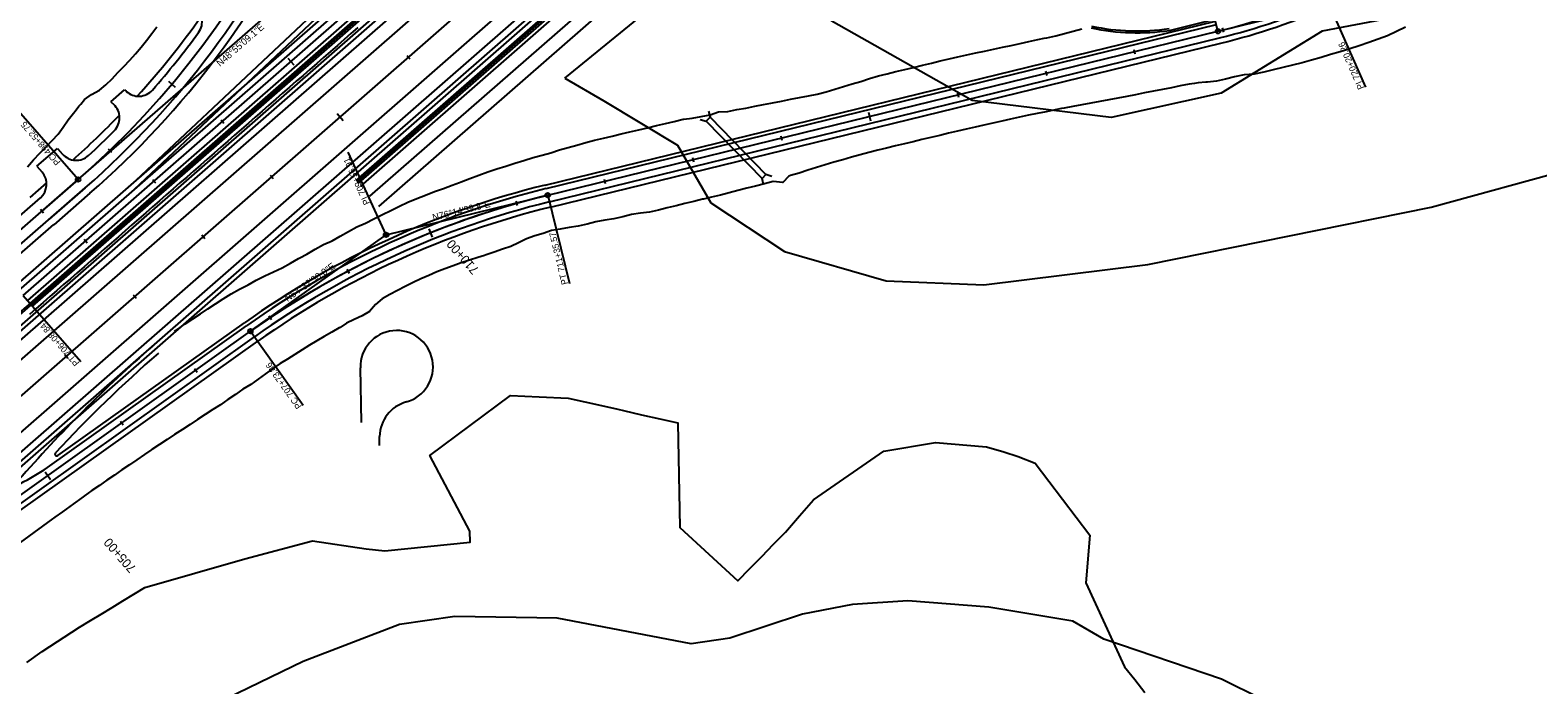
# Model space of a CAD drawing. Extents: x 1300404 to 1323571, y 234004 to 252077.
# Drawn here: x 1309592 to 1311251, y 239629 to 240349 of the extents above; entities that cross this region are included whole.
import ezdxf

# ---------------------------------------------------------------- set-up
doc = ezdxf.new("R2010")
doc.units = 0
for name, color, linetype in [('R_Barrier Wall', 7, 'Continuous'), ('R_Box Culvert', 7, 'Continuous'), ('R_Const Limits', 7, 'Continuous'), ('R_Draft', 7, 'Continuous'), ('R_Flooplain', 7, 'Continuous'), ('R_Future', 7, 'Continuous'), ('R_Horz Alg Annot', 7, 'Continuous'), ('R_Horz Alg Annot Leader', 7, 'Continuous'), ('R_Horz Alg Major Ticks', 7, 'Continuous'), ('R_Horz Alg Minor Ticks', 7, 'Continuous'), ('R_Horz Alg Station Annot', 7, 'Continuous'), ('R_Horz Alg Tangents', 7, 'Continuous'), ('R_Horz Alg Tangents Text', 7, 'Continuous'), ('R_Lane Edge', 7, 'Continuous'), ('R_Proposed', 7, 'Continuous'), ('R_Shoulder', 7, 'Continuous')]:
    doc.layers.add(name, color=color, linetype=linetype)

msp = doc.modelspace()

# ---------------------------------------------------------------- linework, layer by layer
at = {"layer": 'R_Barrier Wall'}
for p, q in [((1309593.6, 240046.8), (1310899.2, 241188.4)), ((1309594.9, 240045.3), (1310900.5, 241186.9)), ((1309593.6, 240046.8), (1309594.9, 240045.3))]:
    msp.add_line(p, q, dxfattribs=at)
at = {"layer": 'R_Box Culvert'}
for p, q in [((1310338.6, 240259.8), (1310340.3, 240253.1)), ((1310329.3, 240250.8), (1310336, 240248.9)), ((1310340.3, 240253.1), (1310336, 240248.9)), ((1310336, 240248.9), (1310397.4, 240185.8)), ((1310340.3, 240253.1), (1310401.7, 240190)), ((1310401.7, 240190), (1310397.4, 240185.8)), ((1310399.1, 240179.1), (1310397.4, 240185.8)), ((1310408.3, 240188.1), (1310401.7, 240190))]:
    msp.add_line(p, q, dxfattribs=at)
at = {"layer": 'R_Const Limits'}
for points in [[(1311105.3, 240352.3), (1311095.4, 240347.4), (1311085.4, 240342.8), (1311075.1, 240339), (1311064.7, 240335.3), (1311054.3, 240331.7), (1311043.9, 240328.3), (1311042.8, 240328), (1311033.3, 240325.3), (1311022.7, 240322.4), (1311012.4, 240318.9), (1311001.9, 240315.9), (1310991.4, 240313.2), (1310980.8, 240310.6), (1310970.2, 240308.1), (1310959.7, 240305.5), (1310949.2, 240302.9), (1310938.6, 240300.6), (1310927.6, 240300), (1310917.2, 240297.5), (1310907.1, 240294.9), (1310897.3, 240293), (1310887.3, 240291.9), (1310885.6, 240291.7), (1310877.2, 240290.9), (1310872.9, 240290.3), (1310867.3, 240289.5), (1310857.4, 240287.6), (1310847.7, 240285.5), (1310837.8, 240283.6), (1310827.9, 240281.9), (1310818.1, 240280), (1310808.3, 240278), (1310798.5, 240276.1), (1310788.7, 240274.1), (1310778.8, 240272.2), (1310768.9, 240270.6), (1310759.1, 240268.7), (1310749.2, 240267), (1310739.4, 240265), (1310729.6, 240263.2), (1310726.7, 240262.7), (1310719.7, 240261.3), (1310709.9, 240259.3), (1310700.1, 240257.4), (1310690.3, 240255.3), (1310680.6, 240253.1), (1310670.8, 240251), (1310661, 240248.8), (1310651.3, 240246.6), (1310641.5, 240244.4), (1310631.8, 240242.2), (1310622, 240240), (1310612.3, 240237.7), (1310602.5, 240235.5), (1310592.8, 240233.2), (1310583, 240230.9), (1310573.3, 240228.6), (1310563.6, 240226.3), (1310553.9, 240223.9), (1310544.2, 240221.6), (1310534.4, 240219.2), (1310524.7, 240216.8), (1310515, 240214.3), (1310505.4, 240211.7), (1310495.7, 240209.1), (1310486.1, 240206.4), (1310476.4, 240203.7), (1310466.9, 240200.8), (1310457.3, 240197.8), (1310447.7, 240194.8), (1310438.2, 240191.8), (1310428.6, 240188.9), (1310426.8, 240188.3), (1310420.2, 240181.2), (1310409.6, 240182.6), (1310399.9, 240180), (1310390.2, 240177.5), (1310380.5, 240175.1), (1310370.8, 240172.7), (1310361.1, 240170.1), (1310351.5, 240167.6), (1310341.7, 240165.2), (1310332.8, 240163.1), (1310332, 240162.9), (1310322.3, 240160.5), (1310312.6, 240158.2), (1310302.9, 240155.8), (1310293.1, 240153.5), (1310283.4, 240151.1), (1310273.7, 240148.8), (1310263.7, 240147.7), (1310253.8, 240146), (1310244.1, 240143.7), (1310234.3, 240141.4), (1310224.4, 240139.9), (1310214.6, 240138), (1310204.9, 240135.6), (1310195.1, 240133.3), (1310185.2, 240131.7), (1310175.3, 240130.1), (1310165.6, 240128.5), (1310156.6, 240125.3), (1310147.4, 240122.5), (1310138.3, 240119.4), (1310129.6, 240115), (1310120.9, 240111), (1310111.8, 240107.9), (1310102.8, 240104.8), (1310093.8, 240101.6), (1310092.1, 240101), (1310084.7, 240098.8), (1310075.5, 240096), (1310066.5, 240093), (1310057.5, 240089.7), (1310048.6, 240086.3), (1310039.7, 240082.9), (1310030.8, 240079.2), (1310022.1, 240075.4), (1310013.5, 240071.2), (1310004.9, 240066.9), (1309996.4, 240062.6), (1309988, 240058.1), (1309979.6, 240053.5), (1309972.1, 240047.3), (1309965.5, 240039.4), (1309957.4, 240034.5), (1309948.8, 240030.5), (1309940.1, 240026.5), (1309933.4, 240021.9), (1309932.2, 240021.3), (1309924, 240016.6), (1309915.8, 240011.9), (1309907.7, 240007), (1309899.4, 240002.3), (1309891.4, 239997.1), (1309883.4, 239992.1), (1309875.3, 239987.1), (1309867.3, 239982.1), (1309859.2, 239976.6), (1309851, 239970.9), (1309843, 239964.9), (1309834.9, 239959.1), (1309826.3, 239953.8), (1309818.1, 239948.1), (1309809.8, 239942.6), (1309801.8, 239936.6), (1309793.1, 239931.6), (1309784.7, 239926.1), (1309776.5, 239920.4), (1309768.2, 239914.9), (1309759.8, 239909.4), (1309751.2, 239904.2), (1309742.9, 239898.6), (1309734.6, 239893.1), (1309726.2, 239887.5), (1309725.1, 239886.7), (1309718, 239881.9), (1309709.7, 239876.3), (1309701.5, 239870.6), (1309693.2, 239865), (1309685, 239859.3), (1309676.7, 239853.7), (1309668.4, 239848), (1309660.2, 239842.3), (1309652.1, 239836.5), (1309645, 239831.5), (1309643.9, 239830.7), (1309635.8, 239824.9), (1309627.7, 239819), (1309619.6, 239813.1), (1309611.5, 239807.3), (1309284.5, 239568.2)], [(1309589.2, 240198.7), (1309596, 240206.3), (1309602.8, 240213.6), (1309606.8, 240217.7), (1309609.8, 240220.8), (1309616.6, 240227.7), (1309623.1, 240234.6), (1309628.7, 240242.4), (1309634.1, 240250.5), (1309640.1, 240257.8), (1309641.8, 240259.8), (1309646, 240265.2), (1309647.9, 240267.6), (1309651.9, 240272.6), (1309659.7, 240278.1), (1309668.4, 240282.8), (1309675.7, 240288.8), (1309682.4, 240295.5), (1309688.9, 240302.4), (1309695.4, 240309.2), (1309701.9, 240316.1), (1309708.3, 240323.1), (1309714.5, 240330.2), (1309720.3, 240337.6), (1309726, 240345.2), (1309731.7, 240352.8)], [(1309952.8, 240352), (1309945.2, 240345.4), (1309937.7, 240338.8), (1309930.2, 240332.3), (1309922.6, 240325.7), (1309915.1, 240319.1), (1309907.6, 240312.5), (1309900.1, 240305.9), (1309892.5, 240299.3), (1309885, 240292.8), (1309877.5, 240286.2), (1309869.9, 240279.6), (1309862.4, 240273), (1309854.9, 240266.4), (1309847.4, 240259.9), (1309839.8, 240253.3), (1309832.3, 240246.7), (1309824.8, 240240.1), (1309817.2, 240233.5), (1309809.7, 240226.9), (1309802.2, 240220.4), (1309794.7, 240213.8), (1309787.1, 240207.2), (1309779.6, 240200.6), (1309772.1, 240194), (1309764.6, 240187.4), (1309757, 240180.9), (1309749.5, 240174.3), (1309742, 240167.7), (1309734.4, 240161.1), (1309726.9, 240154.5), (1309719.4, 240147.9), (1309711.9, 240141.4), (1309704.3, 240134.8), (1309696.8, 240128.2), (1309689.3, 240121.6), (1309681.7, 240115), (1309674.2, 240108.5), (1309666.7, 240101.9), (1309659.2, 240095.3), (1309651.6, 240088.7), (1309644.1, 240082.1), (1309636.6, 240075.5), (1309629.1, 240069), (1309621.5, 240062.4), (1309614, 240055.8), (1309606.5, 240049.2), (1309598.9, 240042.6), (1309591.4, 240036)], [(1309751.2, 240017.8), (1309754.6, 240020.1), (1309762.9, 240025.7), (1309771.2, 240031.2), (1309779.6, 240036.7), (1309787.9, 240042.3), (1309796.2, 240047.8), (1309804.7, 240053.2), (1309813.3, 240058.8), (1309822.6, 240063.9), (1309832, 240068.7), (1309841, 240073.9), (1309850.5, 240078.5), (1309860, 240083.1), (1309869.6, 240087.3), (1309878.6, 240092.5), (1309887.6, 240097.6), (1309888.9, 240098.3), (1309896.8, 240102.6), (1309905.7, 240107.9), (1309914.8, 240113), (1309924.4, 240117.1), (1309933.4, 240122.4), (1309942.4, 240127.6), (1309951.6, 240132.6), (1309961.2, 240136.5), (1309970.5, 240141.3), (1309979.7, 240146.1), (1309989.1, 240150.6), (1309998.4, 240155.3), (1310007.9, 240159.6), (1310017.5, 240163.6), (1310027.2, 240167.6), (1310036.9, 240171.3), (1310046.8, 240174.7), (1310056.5, 240178.4), (1310064.4, 240181.4), (1310066.3, 240182), (1310076, 240185.8), (1310085.8, 240189.4), (1310095.6, 240193.2), (1310105.5, 240196.4), (1310115.5, 240199.5), (1310125.5, 240202.5), (1310135.5, 240205.6), (1310145.5, 240208.7), (1310155.4, 240211.5), (1310165, 240214.2), (1310174.6, 240217.2), (1310184.2, 240220), (1310193.8, 240222.6), (1310203.5, 240225.4), (1310213.1, 240228), (1310222.9, 240230.2), (1310232.6, 240232.5), (1310242.4, 240234.8), (1310252.1, 240237.1), (1310261.8, 240239.4), (1310271.5, 240241.7), (1310281.3, 240244), (1310291, 240246.3), (1310300.8, 240248.5), (1310310.5, 240250.9), (1310311.3, 240251.1), (1310320.5, 240252.1), (1310330.3, 240253.9), (1310340.2, 240255.7), (1310349.6, 240259.2), (1310359.8, 240259.5), (1310369.6, 240261.6), (1310379.5, 240263.3), (1310389.3, 240265.3), (1310399.1, 240267.2), (1310407.1, 240268.7), (1310409, 240269), (1310418.8, 240270.9), (1310428.6, 240272.9), (1310438.5, 240274.8), (1310448.3, 240276.8), (1310458.1, 240278.7), (1310467.8, 240281.3), (1310477.3, 240284.2), (1310486.9, 240287.1), (1310496.5, 240290.1), (1310506.2, 240292.6), (1310515.7, 240295.7), (1310525.3, 240298.6), (1310535, 240301), (1310544.7, 240303.4), (1310554.4, 240305.8), (1310564.1, 240308.1), (1310573.9, 240310.5), (1310583.6, 240312.8), (1310593.3, 240315.1), (1310603.1, 240317.3), (1310612.8, 240319.5), (1310622.6, 240321.7), (1310632.4, 240323.9), (1310642.1, 240326), (1310651.9, 240328.1), (1310661.7, 240330.2), (1310671.5, 240332.3), (1310681.3, 240334.3), (1310691, 240336.4), (1310700.8, 240338.6), (1310707.7, 240340.1), (1310710.6, 240340.7), (1310720.4, 240342.8), (1310730.1, 240345.3), (1310739.7, 240348), (1310749.3, 240350.6)], [(1309588.6, 239653), (1309605.6, 239665.2), (1309646.5, 239691.9), (1309658.5, 239699.2), (1309670.5, 239706.4), (1309682.5, 239713.7), (1309694.4, 239721), (1309706.4, 239728.3), (1309718.4, 239735.6), (1309828.3, 239767.1), (1309903, 239787.2), (1309961.9, 239778.3), (1309982.5, 239775.9), (1310076.4, 239785.5), (1310075.8, 239797.7), (1310031.9, 239880.8), (1310120.8, 239947), (1310136.5, 239946.2), (1310152.1, 239945.4), (1310184.2, 239944.2), (1310202.4, 239940.1), (1310220.6, 239936), (1310238.7, 239931.9), (1310244.8, 239930.3), (1310264.8, 239925.8), (1310284.9, 239921.3), (1310304.6, 239917), (1310307.1, 239801.8), (1310370.8, 239743.2), (1310383.9, 239756.6), (1310397, 239769.9), (1310410.1, 239783.3), (1310423.2, 239796.7), (1310438.6, 239814.5), (1310454.1, 239832.3), (1310531.2, 239885.6), (1310588.1, 239895.4), (1310644.2, 239890.6), (1310663.3, 239885), (1310679, 239879.8), (1310697.7, 239872.5), (1310757.9, 239793.2), (1310753.7, 239740.9), (1310796.2, 239648.5), (1310807.3, 239634.4), (1310818.3, 239620.3)]]:
    msp.add_lwpolyline(points, dxfattribs=at)
at = {"layer": 'R_Draft'}
for p, q in [((1308397, 238971.9), (1312368.4, 242444.5)), ((1308407.8, 238959.5), (1312379.2, 242432.1)), ((1308447.3, 238914.3), (1312418.7, 242386.9)), ((1308458.2, 238901.9), (1312429.6, 242374.5)), ((1309184.5, 239689.1), (1312131.4, 242265.9)), ((1309037.8, 239548.2), (1312137.6, 242258.7)), ((1309193.7, 239678.5), (1312140.6, 242255.3)), ((1309413.9, 239721.6), (1312065.7, 242040.4)), ((1309410.9, 239725), (1311988, 241978.4)), ((1309410.9, 239725), (1311988, 241978.4))]:
    msp.add_line(p, q, dxfattribs=at)
at = {"layer": 'R_Flooplain'}
for p, q in [((1310180.4, 240296), (1310403.6, 240478.3)), ((1310628.6, 240271.6), (1310473.3, 240359.3)), ((1311123.4, 240368.9), (1311013.5, 240347.8)), ((1311013.5, 240347.8), (1310902.4, 240279.6)), ((1310180.4, 240296), (1310223.3, 240271.4)), ((1310902.4, 240279.6), (1310781.3, 240253)), ((1310223.3, 240271.4), (1310304.4, 240222.6)), ((1310781.3, 240253), (1310628.6, 240271.6)), ((1311133.3, 240154.2), (1311385.9, 240223.8)), ((1310304.4, 240222.6), (1310341.1, 240159)), ((1310341.1, 240159), (1310421.9, 240105.4)), ((1310821.6, 240091.3), (1311133.3, 240154.2)), ((1310421.9, 240105.4), (1310534, 240073.1)), ((1310641.5, 240068.9), (1310821.6, 240091.3)), ((1310534, 240073.1), (1310641.5, 240068.9)), ((1310496.9, 239716.9), (1310442, 239706.3)), ((1310557.6, 239721.1), (1310496.9, 239716.9)), ((1310646.8, 239714.2), (1310557.6, 239721.1)), ((1310739.2, 239698.6), (1310646.8, 239714.2)), ((1309998.6, 239694.8), (1309892.5, 239654.2)), ((1310059.5, 239703.8), (1309998.6, 239694.8)), ((1310171.9, 239701.8), (1310059.5, 239703.8)), ((1310319.4, 239673.8), (1310171.9, 239701.8)), ((1310442, 239706.3), (1310362, 239680.1)), ((1310773.3, 239678.8), (1310739.2, 239698.6)), ((1310362, 239680.1), (1310319.4, 239673.8)), ((1310902.9, 239634.7), (1310773.3, 239678.8)), ((1309892.5, 239654.2), (1309772.3, 239596.1)), ((1311061.2, 239556.6), (1310902.9, 239634.7))]:
    msp.add_line(p, q, dxfattribs=at)
at = {"layer": 'R_Future'}
for p, q in [((1311714.8, 241726.2), (1309950.4, 240183.5)), ((1311716.1, 241724.7), (1309951.7, 240182)), ((1311717.4, 241723.2), (1309953.1, 240180.5)), ((1311720, 241720.2), (1309955.7, 240177.5)), ((1310616.7, 240735.5), (1309965.6, 240166.2)), ((1310582.5, 240685.7), (1309975.4, 240154.9)), ((1309920.8, 240383.4), (1309702.3, 240177.7)), ((1309924.9, 240379), (1309706.3, 240173.3)), ((1310845.6, 240348.7), (1310895.6, 240361))]:
    msp.add_line(p, q, dxfattribs=at)
for radius, end in [(249, 278.1831), (247, 278.1605)]:
    msp.add_arc((1310810.1, 240595.2), radius, 258.2643, end, dxfattribs=at)
at = {"layer": 'R_Horz Alg Annot Leader'}
for points in [[(1310898.9, 240347.8), (1310875.1, 240445)], [(1311021, 240377.7), (1311061.2, 240286.2)], [(1309645, 240184.6), (1309579.3, 240260)], [(1309983.8, 240123.8), (1309942.2, 240214.8)], [(1310161.6, 240167.4), (1310185.4, 240070.2)], [(1309584.7, 240057), (1309648.2, 239984.4)], [(1309834.7, 240017.7), (1309892.7, 239936.2)]]:
    msp.add_lwpolyline(points, dxfattribs=at)
at = {"layer": 'R_Horz Alg Major Ticks'}
for points in [[(1309875.9, 240318.2), (1309882.5, 240310.7)], [(1309744.3, 240292.8), (1309751.9, 240286.3)], [(1309929.9, 240257.2), (1309936.5, 240249.6)], [(1310514.4, 240258.9), (1310516.8, 240249.2)], [(1310030.8, 240130.5), (1310034.5, 240121.3)], [(1309608.8, 239862.9), (1309614.6, 239854.7)]]:
    msp.add_lwpolyline(points, dxfattribs=at)
at = {"layer": 'R_Horz Alg Minor Ticks'}
for points in [[(1310903.5, 240351.6), (1310904.8, 240346.7)], [(1310806.4, 240327.8), (1310807.6, 240322.9)], [(1310006.8, 240321.1), (1310010.1, 240317.4)], [(1310709.3, 240304), (1310710.5, 240299.2)], [(1310612.2, 240280.2), (1310613.3, 240275.4)], [(1309802.3, 240250.5), (1309805.5, 240246.8)], [(1310417.9, 240232.7), (1310419.1, 240227.8)], [(1309678.1, 240218.4), (1309681.6, 240214.8)], [(1310320.8, 240208.9), (1310321.9, 240204)], [(1309727, 240184.7), (1309730.3, 240180.9)], [(1309856.2, 240189.5), (1309859.5, 240185.7)], [(1310223.6, 240185.1), (1310224.8, 240180.3)], [(1310126.6, 240160.7), (1310127.9, 240155.9)], [(1309603.6, 240151.9), (1309606.9, 240148.1)], [(1309651.7, 240118.9), (1309655, 240115.1)], [(1309781, 240123.6), (1309784.3, 240119.9)], [(1309940.8, 240086.1), (1309943.2, 240081.6)], [(1309705.7, 240057.8), (1309709, 240054.1)], [(1309854.8, 240034.6), (1309857.6, 240030.5)], [(1309630.4, 239992), (1309633.7, 239988.2)], [(1309773.1, 239976.8), (1309776, 239972.8)], [(1309691.7, 239918.8), (1309694.6, 239914.8)]]:
    msp.add_lwpolyline(points, dxfattribs=at)
at = {"layer": 'R_Horz Alg Tangents'}
for p, q in [((1309645, 240184.6), (1309967.2, 240465.5)), ((1310898.9, 240347.8), (1311021, 240377.7)), ((1309983.8, 240123.8), (1310161.6, 240167.4)), ((1309834.7, 240017.7), (1309983.8, 240123.8))]:
    msp.add_line(p, q, dxfattribs=at)
at = {"layer": 'R_Lane Edge'}
for p, q in [((1309579.8, 240062.7), (1310885.3, 241204.2)), ((1309589.7, 240051.4), (1310895.2, 241193)), ((1310159.9, 240174.7), (1310897.1, 240355.1)), ((1310163.4, 240160.1), (1310900.6, 240340.6)), ((1309681, 240270.2), (1309696.2, 240283.4)), ((1309696.2, 240283.4), (1309698, 240281.7)), ((1309681, 240270.2), (1309684.4, 240267.1)), ((1309599.8, 240199.2), (1309622.4, 240218.9)), ((1309622.4, 240218.9), (1309627.9, 240212.6)), ((1309599.8, 240199.2), (1309605.5, 240192.7)), ((1309462.4, 240009.5), (1309652.9, 240175.6)), ((1309652.9, 240175.6), (1309613.1, 240140.9)), ((1309446.6, 240027.6), (1309603.6, 240164.4)), ((1309603.6, 240164.4), (1309597.3, 240159)), ((1309374.6, 239680.8), (1309839.1, 240011.5)), ((1309611.4, 239867.8), (1309830.4, 240023.8)), ((1309956.9, 239917.2), (1309955.5, 239977.6)), ((1309976.5, 239891.9), (1309976.7, 239901.9))]:
    msp.add_line(p, q, dxfattribs=at)
for centre, radius, start, end in [((1309017.5, 240904.4), 966.9, 311.0808, 359.305), ((1310728.6, 241043.5), 723.7, 283.7556, 303.6667), ((1309761.5, 240358.3), 20, 323.7218, 55.5845), ((1309017.5, 240904.4), 942.9, 318.7813, 323.7218), ((1309711.7, 240296.3), 20, 226.9186, 318.7813), ((1309670.7, 240252.5), 20, 315.0558, 46.9186), ((1309017.5, 240904.4), 942.9, 312.6643, 315.0558), ((1309643, 240225.8), 20, 221.0808, 312.6643), ((1309590.4, 240179.5), 20, 311.0808, 41.0808), ((1310388.7, 239239.8), 962.4, 103.7556, 125.4583), ((1310388.7, 239239.8), 947.4, 103.7556, 125.4583), ((1309995.5, 239978.5), 40, 285.332, 181.2933), ((1310770.2, 238812.1), 1582, 131.2681, 138.8338), ((1310016.7, 239901.3), 40, 105.332, 179.1602), ((1309486.7, 240046), 217.5, 295.8741, 304.9655)]:
    msp.add_arc(centre, radius, start, end, dxfattribs=at)
at = {"layer": 'R_Proposed'}
for p, q in [((1308463.1, 238968), (1312793.8, 242754.8)), ((1308427.6, 238936.9), (1312399, 242409.5)), ((1309180.4, 239595.2), (1312399, 242409.5)), ((1309180.4, 239595.2), (1312399, 242409.5)), ((1309180.4, 239595.2), (1312051.5, 242105.7)), ((1309584.7, 240057), (1310889.7, 241198)), ((1310161.6, 240167.4), (1310898.9, 240347.8)), ((1310161.6, 240167.4), (1310898.9, 240347.8)), ((1309454.5, 240018.5), (1309645, 240184.6)), ((1309645, 240184.6), (1309605.2, 240150)), ((1309370.3, 239686.9), (1309834.7, 240017.7)), ((1309370.3, 239686.9), (1309834.7, 240017.7)), ((1309370.3, 239686.9), (1309834.7, 240017.7)), ((1309370.3, 239686.9), (1309834.7, 240017.7)), ((1309370.3, 239686.9), (1309834.7, 240017.7))]:
    msp.add_line(p, q, dxfattribs=at)
for centre in [(1310898.9, 240347.8), (1309645, 240184.6), (1310161.6, 240167.4), (1309983.8, 240123.8), (1309834.7, 240017.7)]:
    msp.add_circle(centre, 2.5, dxfattribs=at)
for centre, radius, start, end in [((1309017.5, 240904.4), 954.9, 311.0808, 359.305), ((1309017.5, 240904.4), 954.9, 311.0808, 359.305), ((1310728.6, 241043.5), 716.2, 283.7556, 303.6667), ((1310728.6, 241043.5), 716.2, 283.7556, 303.6667), ((1310388.7, 239239.8), 954.9, 103.7556, 125.4583), ((1310388.7, 239239.8), 954.9, 103.7556, 125.4583), ((1310388.7, 239239.8), 954.9, 104.2118, 125.4583), ((1310388.7, 239239.8), 954.9, 104.2118, 125.4583), ((1310388.7, 239239.8), 954.9, 104.2118, 125.4583)]:
    msp.add_arc(centre, radius, start, end, dxfattribs=at)
at = {"layer": 'R_Shoulder'}
for p, q in [((1309575.8, 240067.2), (1310881.4, 241208.7)), ((1309592.3, 240048.3), (1310897.9, 241189.9)), ((1310158.9, 240178.5), (1310896.1, 240359)), ((1310164.8, 240154.3), (1310902.1, 240334.7)), ((1309610.4, 240181), (1309592, 240165)), ((1309658.1, 240169.6), (1309618.3, 240134.9)), ((1309467.6, 240003.5), (1309618.2, 240135.1)), ((1309622.8, 239880.8), (1309828.1, 240027)), ((1309378.1, 239675.9), (1309842.6, 240006.7))]:
    msp.add_line(p, q, dxfattribs=at)
for centre, radius, start, end in [((1309017.5, 240904.4), 974.9, 311.0808, 359.305), ((1310728.6, 241043.5), 729.7, 283.7556, 303.6667), ((1309017.5, 240904.4), 934.9, 317.7944, 324.7087), ((1309017.5, 240904.4), 934.9, 311.6774, 316.0427), ((1310388.7, 239239.8), 966.4, 103.7556, 125.4583), ((1310388.7, 239239.8), 941.4, 103.7556, 125.4583), ((1313356.2, 235743.8), 5718.1, 131.1667, 133.9285), ((1310770.2, 238812.1), 1572, 131.2681, 137.0202), ((1309621.6, 239882.4), 2, 137.0202, 305.4583)]:
    msp.add_arc(centre, radius, start, end, dxfattribs=at)

# ---------------------------------------------------------------- texts
at = {"layer": 'R_Horz Alg Annot'}
for s, rotation, p in [('PI 720+20.26', 113.7111, (1311059.8, 240285.6)), ('PC 498+52.75', 131.0808, (1309626.1, 240204)), ('PI 709+56.91', 114.607, (1309966.2, 240158.7)), ('PT 711+35.57', 103.7556, (1310184, 240069.9)), ('PT 706+08.84', 131.1667, (1309646.9, 239983.1)), ('PC 707+73.86', 125.4583, (1309891.5, 239935.3))]:
    msp.add_text(s, height=7, rotation=rotation, dxfattribs=at).set_placement(p)
at = {"layer": 'R_Horz Alg Station Annot'}
for s, p in [('710+00', (1310086.6, 240085.7)), ('705+00', (1309709.5, 239757.3))]:
    msp.add_text(s, height=10, rotation=131.1667, dxfattribs=at).set_placement(p)
at = {"layer": 'R_Horz Alg Tangents Text'}
for s, rotation, p in [('N48%%d55\'09.1"E', 41.0808, (1309801.2, 240308.5)), ('N76%%d14\'39.8"E', 13.7556, (1310035.8, 240139.1)), ('N54%%d32\'30.0"E', 35.4583, (1309875.5, 240049.8))]:
    msp.add_text(s, height=7.5, rotation=rotation, dxfattribs=at).set_placement(p)

doc.saveas('drawing.dxf')
